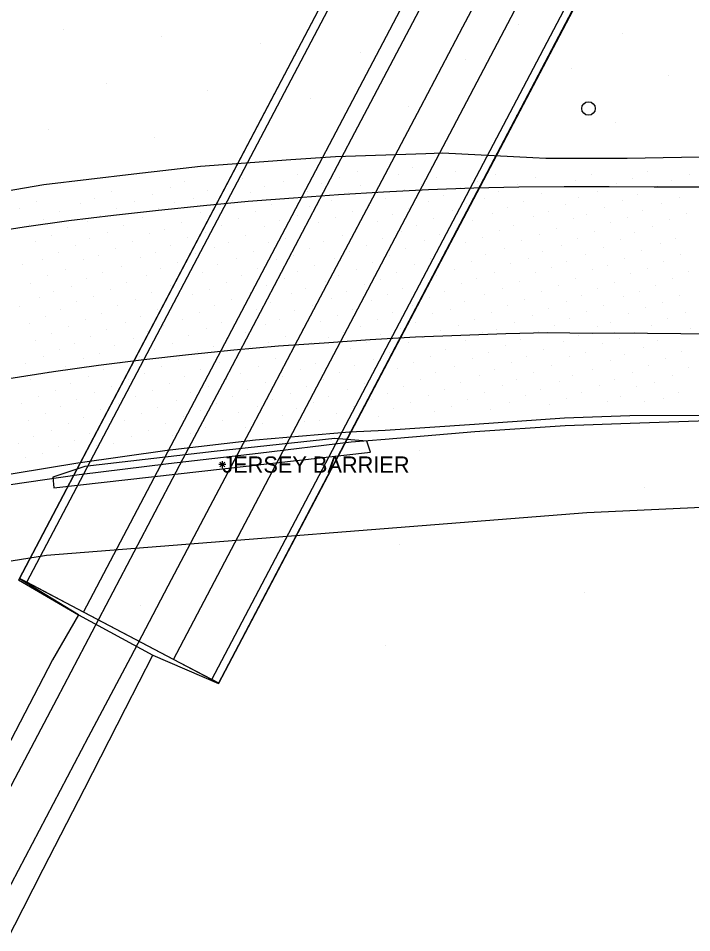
# Model space of a CAD drawing. Extents: x 1732346 to 1733076, y 467730 to 468633.
# Drawn here: x 1732639.2 to 1732713.8, y 467892.4 to 467993.7 of the extents above; entities that cross this region are included whole.
import ezdxf

# ---------------------------------------------------------------- set-up
doc = ezdxf.new("R2010")
doc.units = 0
for name, color, linetype in [('Default', 7, 'Continuous'), ('S_Bridge_BoxCulvert', 7, 'Continuous'), ('S_Ground_Elevation', 7, 'Continuous'), ('S_Ground_LevelString', 7, 'Continuous'), ('S_Ground_SpotElevation', 7, 'Continuous'), ('S_Guardrail_Beam', 7, 'Continuous'), ('S_Guardrail_JerseyBarrier', 7, 'Continuous'), ('S_Misc_MiscItems', 7, 'Continuous'), ('S_Railroad_Tracks', 7, 'Continuous'), ('S_Roadway_Edge_Pavement', 7, 'Continuous'), ('S_Roadway_Painted_Lines', 7, 'Continuous'), ('S_Text', 7, 'Continuous'), ('S_Traffic_Posts', 7, 'Continuous'), ('S_Trees_Bush_Line', 7, 'Continuous'), ('TopoDOT Temp', 7, 'Continuous')]:
    doc.layers.add(name, color=color, linetype=linetype)

# ---------------------------------------------------------------- blocks, each defined once
blk = doc.blocks.new('POINT_DISPLAY')
at = {"layer": 'Default'}
blk.add_line((0, 0), (0, 0), dxfattribs=at)

msp = doc.modelspace()

# ---------------------------------------------------------------- linework, layer by layer
at = {"layer": 'S_Bridge_BoxCulvert'}
for p, q in [((1732639.35, 467931.59), (1732772.73, 468185.16)), ((1732639.36, 467931.62), (1732772.74, 468185.19)), ((1732640.16, 467931.2), (1732773.54, 468184.77)), ((1732646.44, 467927.9), (1732779.82, 468181.46)), ((1732656.4, 467922.66), (1732789.78, 468176.22)), ((1732660.64, 467920.43), (1732794.02, 468173.99)), ((1732661.39, 467920), (1732794.77, 468173.57)), ((1732661.44, 467920.01), (1732794.82, 468173.57)), ((1732639.59, 467932.1), (1732639.59, 467932.1)), ((1732662.35, 467921.99), (1732662.35, 467921.99))]:
    msp.add_line(p, q, dxfattribs=at)
msp.add_lwpolyline([(1732661.39, 467920), (1732661.44, 467920.01), (1732660.64, 467920.43), (1732656.4, 467922.66), (1732646.44, 467927.9), (1732640.16, 467931.2), (1732639.36, 467931.62), (1732639.35, 467931.59)], dxfattribs=at)
at = {"layer": 'S_Ground_Elevation'}
for points in [[(1732645.88, 467927.6), (1732643.01, 467922.59), (1732638.39, 467913.72), (1732633.76, 467904.86), (1732631.44, 467900.41), (1732626.81, 467891.55), (1732622.18, 467882.68), (1732617.56, 467873.82), (1732615.12, 467869.15), (1732610.49, 467860.28), (1732605.86, 467851.42), (1732603.58, 467847.03)], [(1732612.36, 467841.68), (1732616.92, 467850.58), (1732621.49, 467859.48), (1732626.05, 467868.38), (1732630.62, 467877.27), (1732635.18, 467886.17), (1732639.75, 467895.07), (1732641.98, 467899.42), (1732646.55, 467908.32), (1732651.11, 467917.22), (1732654.14, 467923.12)]]:
    msp.add_lwpolyline(points, dxfattribs=at)
at = {"layer": 'S_Ground_LevelString'}
for p, q in [((1732639.24, 467931.46), (1732639.35, 467931.59)), ((1732639.24, 467931.46), (1732645.88, 467927.6)), ((1732639.36, 467931.62), (1732639.35, 467931.59)), ((1732645.88, 467927.6), (1732639.35, 467931.59)), ((1732645.88, 467927.6), (1732654.14, 467923.12)), ((1732654.14, 467923.12), (1732661.39, 467920))]:
    msp.add_line(p, q, dxfattribs=at)
msp.add_lwpolyline([(1732639.36, 467931.62), (1732640.16, 467931.2), (1732660.64, 467920.43), (1732661.44, 467920.01), (1732661.39, 467920)], dxfattribs=at)
at = {"layer": 'S_Guardrail_Beam'}
msp.add_lwpolyline([(1732716.65, 467949.12), (1732706.99, 467948.77), (1732699.77, 467948.52), (1732689.79, 467947.86), (1732679.84, 467947.01), (1732676.08, 467946.7), (1732665.79, 467945.45), (1732655.86, 467944.31), (1732645.98, 467943.08), (1732628.68, 467940.59), (1732625.06, 467940.03), (1732617.13, 467938.47), (1732607.4, 467936.29), (1732607.28, 467936.26), (1732588.1, 467930.71)], dxfattribs=at)
at = {"layer": 'S_Guardrail_JerseyBarrier'}
msp.add_lwpolyline([(1732678.23, 467945.61), (1732677.84, 467946.82), (1732674.27, 467947.12), (1732660.9, 467945.69), (1732646.6, 467944), (1732643.05, 467942.83), (1732643.16, 467941.67), (1732678.23, 467945.61)], dxfattribs=at)
at = {"layer": 'S_Misc_MiscItems'}
for p, q in [((1732662.08, 467943.97), (1732661.56, 467944.49)), ((1732662.08, 467944.49), (1732661.56, 467943.97)), ((1732661.82, 467944.62), (1732661.82, 467943.84)), ((1732662.21, 467944.23), (1732661.43, 467944.23))]:
    msp.add_line(p, q, dxfattribs=at)
at = {"layer": 'S_Railroad_Tracks'}
for points in [[(1732693.1, 468001.52), (1732688.43, 467992.68), (1732683.77, 467983.83), (1732679.11, 467974.98), (1732674.44, 467966.14), (1732669.78, 467957.29), (1732665.11, 467948.45), (1732660.45, 467939.6), (1732655.79, 467930.75), (1732651.64, 467922.88), (1732646.97, 467914.03), (1732642.31, 467905.19), (1732637.65, 467896.34), (1732636.52, 467894.21), (1732631.86, 467885.36)], [(1732627.08, 467887.08), (1732631.74, 467895.93), (1732634.22, 467900.64), (1732638.87, 467909.49), (1732643.53, 467918.34), (1732648.19, 467927.19), (1732652.84, 467936.04), (1732657.5, 467944.89), (1732662.16, 467953.74), (1732666.82, 467962.59), (1732671.47, 467971.44), (1732676.13, 467980.29), (1732680.79, 467989.14), (1732685.44, 467997.99)]]:
    msp.add_lwpolyline(points, dxfattribs=at)
at = {"layer": 'S_Roadway_Edge_Pavement'}
for points in [[(1732600.62, 467966.95), (1732605.6, 467968.27), (1732615.38, 467970.35), (1732623.8, 467972.14), (1732633.66, 467973.82), (1732642.07, 467975.25), (1732652.01, 467976.42), (1732659.41, 467977.29), (1732669.39, 467978), (1732674.35, 467978.35), (1732684.34, 467978.69), (1732686.22, 467978.76), (1732696.2, 467978.22), (1732697.64, 467978.15), (1732706.25, 467978.15), (1732706.66, 467978.15), (1732716.66, 467978.36)], [(1732587.85, 467931.51), (1732607.07, 467937.03), (1732607.21, 467937.06), (1732616.96, 467939.29), (1732624.9, 467940.88), (1732628.53, 467941.58), (1732645.8, 467944.41), (1732655.7, 467945.83), (1732665.51, 467946.97), (1732675.9, 467947.87), (1732679.84, 467948.06), (1732689.74, 467948.7), (1732699.72, 467949.4), (1732706.95, 467949.66), (1732717.62, 467949.7)]]:
    msp.add_lwpolyline(points, dxfattribs=at)
at = {"layer": 'S_Roadway_Painted_Lines'}
for points in [[(1732714.66, 467974.97), (1732709.66, 467974.97), (1732704.66, 467974.98), (1732699.66, 467974.98), (1732694.66, 467974.95), (1732689.66, 467974.85), (1732684.66, 467974.66), (1732679.67, 467974.39), (1732674.68, 467974.09), (1732669.69, 467973.75), (1732664.7, 467973.35), (1732659.72, 467972.89), (1732654.75, 467972.36), (1732649.78, 467971.81), (1732644.81, 467971.21), (1732639.86, 467970.52), (1732634.91, 467969.76), (1732629.98, 467968.93), (1732625.06, 467968.02), (1732620.15, 467967.05), (1732615.26, 467966.01), (1732610.38, 467964.91), (1732605.52, 467963.74), (1732600.68, 467962.48)], [(1732638.18, 467953.78), (1732643.13, 467954.54), (1732648.1, 467955.23), (1732653.13, 467955.86), (1732658.09, 467956.44), (1732663.08, 467956.94), (1732668.05, 467957.38), (1732673.1, 467957.73), (1732678.2, 467958.1), (1732683.21, 467958.36), (1732688.25, 467958.58), (1732693.2, 467958.73), (1732697.82, 467958.87), (1732702.78, 467958.77), (1732705.2, 467958.82), (1732712.6, 467958.76), (1732717.93, 467958.68)]]:
    msp.add_lwpolyline(points, dxfattribs=at)
at = {"layer": 'S_Traffic_Posts'}
msp.add_circle((1732702.37, 467983.67), 0.749, dxfattribs=at)
at = {"layer": 'S_Trees_Bush_Line'}
for points in [[(1732642.36, 467934.2), (1732702.19, 467938.94), (1732749.16, 467941.12), (1732770.02, 467940.5), (1732820.12, 467934.82), (1732875.32, 467924.75), (1732924.72, 467916.03), (1732963.52, 467908.47), (1733004.95, 467900.18), (1733036.67, 467893.23)], [(1732378.87, 467730.2), (1732418.68, 467785.25), (1732451.46, 467829.57), (1732481.42, 467856.92), (1732516.44, 467887.67), (1732559.01, 467910.48), (1732592.36, 467920.81), (1732609.83, 467928.98), (1732642.36, 467934.2)]]:
    msp.add_lwpolyline(points, dxfattribs=at)
at = {"layer": 'TopoDOT Temp'}
for p, q in [((1732688.43, 467992.68), (1732688.43, 467992.68)), ((1732680.79, 467989.14), (1732680.79, 467989.14)), ((1732683.77, 467983.83), (1732683.77, 467983.83)), ((1732676.13, 467980.29), (1732676.13, 467980.29)), ((1732679.11, 467974.98), (1732679.11, 467974.98)), ((1732671.47, 467971.44), (1732671.47, 467971.44)), ((1732674.44, 467966.14), (1732674.44, 467966.14)), ((1732666.82, 467962.59), (1732666.82, 467962.59)), ((1732669.78, 467957.29), (1732669.78, 467957.29)), ((1732662.16, 467953.74), (1732662.16, 467953.74)), ((1732665.11, 467948.45), (1732665.11, 467948.45)), ((1732657.5, 467944.89), (1732657.5, 467944.89)), ((1732660.45, 467939.6), (1732660.45, 467939.6)), ((1732652.84, 467936.04), (1732652.84, 467936.04)), ((1732655.79, 467930.75), (1732655.79, 467930.75)), ((1732645.88, 467927.6), (1732645.88, 467927.6)), ((1732645.88, 467927.6), (1732645.88, 467927.6)), ((1732648.19, 467927.19), (1732648.19, 467927.19)), ((1732654.14, 467923.12), (1732654.14, 467923.12)), ((1732654.14, 467923.12), (1732654.14, 467923.12)), ((1732643.01, 467922.59), (1732643.01, 467922.59)), ((1732651.64, 467922.88), (1732651.64, 467922.88)), ((1732643.53, 467918.34), (1732643.53, 467918.34)), ((1732651.11, 467917.22), (1732651.11, 467917.22)), ((1732646.97, 467914.03), (1732646.97, 467914.03)), ((1732646.55, 467908.32), (1732646.55, 467908.32)), ((1732642.31, 467905.19), (1732642.31, 467905.19)), ((1732641.98, 467899.42), (1732641.98, 467899.42)), ((1732639.75, 467895.07), (1732639.75, 467895.07))]:
    msp.add_line(p, q, dxfattribs=at)

# ---------------------------------------------------------------- block references
at = {"layer": 'S_Ground_SpotElevation'}
for p in [(1732644.23, 467992.44), (1732694.66, 467992.99), (1732655.04, 467991.64), (1732706.16, 467991.92), (1732666.02, 467990.87), (1732677.13, 467989.89), (1732688.76, 467989.04), (1732700.52, 467988.12), (1732711.25, 467987.34), (1732648.98, 467986.48), (1732660.17, 467985.71), (1732671.57, 467984.72), (1732682.44, 467983.91), (1732694.37, 467982.93), (1732705.33, 467982.14), (1732642.56, 467981.36), (1732654.34, 467980.43), (1732682.85, 467977.1), (1732664.07, 467975.92), (1732670.11, 467976.39), (1732674.81, 467975.99), (1732676.78, 467976.68), (1732681.35, 467976.38), (1732685.57, 467976.02), (1732687.6, 467976.72), (1732692.09, 467976.39), (1732696.54, 467975.99), (1732702.65, 467976.31), (1732707.2, 467975.96), (1732708.91, 467976.67), (1732713.59, 467976.38), (1732656.13, 467974.92), (1732657.65, 467975.55), (1732662.34, 467975.24), (1732666.54, 467975.02), (1732668.62, 467975.63), (1732672.84, 467975.41), (1732677.07, 467975.15), (1732679.37, 467975.62), (1732683.92, 467975.23), (1732688.17, 467974.96), (1732690.12, 467975.59), (1732694.46, 467975.24), (1732699.1, 467975), (1732700.92, 467975.74), (1732705.42, 467975.37), (1732710.01, 467975.07), (1732711.61, 467975.67), (1732649.57, 467974.43), (1732654.08, 467974.16), (1732660.14, 467974.54), (1732664.96, 467974.41), (1732671.2, 467974.46), (1732675.8, 467974.32), (1732682.03, 467974.71), (1732686.27, 467974.05), (1732692.41, 467974.52), (1732697.12, 467974.3), (1732701.31, 467973.8), (1732703.37, 467974.46), (1732707.8, 467974.17), (1732712.44, 467973.77), (1732641.24, 467973.35), (1732646.06, 467973.11), (1732647.61, 467973.68), (1732652.14, 467973.33), (1732656.48, 467973.29), (1732658.62, 467973.73), (1732662.95, 467973.46), (1732667.25, 467972.98), (1732669.05, 467973.7), (1732671.5, 467972.78), (1732673.95, 467973.46), (1732678.12, 467972.93), (1732679.89, 467973.68), (1732684.65, 467973.41), (1732688.83, 467973.11), (1732690.85, 467973.75), (1732695.15, 467973.36), (1732699.82, 467973.02), (1732704.11, 467972.75), (1732706.14, 467973.48), (1732710.51, 467973.09), (1732639.39, 467972.6), (1732643.81, 467972.26), (1732648.32, 467971.83), (1732650.08, 467972.64), (1732654.74, 467972.64), (1732659.41, 467972.16), (1732660.94, 467972.54), (1732665.46, 467972.21), (1732670.16, 467971.87), (1732676.27, 467972.23), (1732680.63, 467971.89), (1732682.43, 467972.61), (1732687.28, 467972.34), (1732691.77, 467972.01), (1732693.37, 467972.73), (1732697.93, 467972.26), (1732702.17, 467971.88), (1732708.37, 467972.32), (1732713.24, 467972.09), (1732640.47, 467970.83), (1732642.07, 467971.41), (1732646.84, 467971.17), (1732650.85, 467970.73), (1732652.96, 467971.57), (1732657.3, 467971.05), (1732661.74, 467970.72), (1732663.62, 467971.45), (1732668.14, 467971.22), (1732672.46, 467971.05), (1732674.37, 467971.56), (1732678.99, 467971.18), (1732685.17, 467971.47), (1732689.58, 467971.21), (1732694.02, 467970.75), (1732696.27, 467971.69), (1732700.67, 467971.46), (1732704.79, 467971), (1732706.7, 467971.58), (1732711.36, 467971.37), (1732644.67, 467970.51), (1732649.12, 467969.98), (1732653.76, 467969.81), (1732655.37, 467970.3), (1732660, 467969.97), (1732666.47, 467970.64), (1732670.67, 467970), (1732676.8, 467970.41), (1732681.67, 467970.08), (1732683.29, 467970.69), (1732687.73, 467970.4), (1732692.51, 467970.17), (1732696.93, 467969.71), (1732698.78, 467970.42), (1732703, 467970.01), (1732707.47, 467969.96), (1732709.51, 467970.58), (1732641.17, 467968.99), (1732642.91, 467969.55), (1732647.15, 467969.24), (1732651.89, 467968.94), (1732657.97, 467969.37), (1732662.46, 467968.87), (1732664.41, 467969.6), (1732666.94, 467968.77), (1732668.84, 467969.25), (1732673.03, 467968.99), (1732675.14, 467969.58), (1732679.56, 467969.32), (1732684.25, 467969.04), (1732685.92, 467969.66), (1732688.75, 467968.8), (1732690.65, 467969.35), (1732694.98, 467969.01), (1732701.2, 467969.27), (1732705.89, 467969.11), (1732710.32, 467968.72), (1732712.01, 467969.3), (1732643.7, 467967.69), (1732645.55, 467968.47), (1732649.98, 467968.11), (1732654.38, 467967.71), (1732656.13, 467968.44), (1732660.97, 467968.3), (1732665.22, 467967.79), (1732671.43, 467968.13), (1732675.85, 467967.79), (1732677.82, 467968.48), (1732682.14, 467968.15), (1732686.43, 467967.85), (1732693.02, 467968.17), (1732697.3, 467967.86), (1732699.42, 467968.5), (1732704.01, 467968.3), (1732708.19, 467967.96), (1732641.87, 467966.98), (1732646.41, 467966.93), (1732648.15, 467967.35), (1732652.75, 467967.16), (1732658.88, 467967.57), (1732663.35, 467967.02), (1732667.77, 467966.91), (1732669.66, 467967.39), (1732674.21, 467967), (1732680.29, 467967.37), (1732684.9, 467967.01), (1732689.45, 467966.68), (1732691.01, 467967.48), (1732695.68, 467967.01), (1732699.96, 467966.71), (1732702.02, 467967.49), (1732706.36, 467967.01), (1732710.73, 467966.7), (1732712.6, 467967.49), (1732639.72, 467966.37), (1732644.5, 467965.86), (1732650.61, 467966.21), (1732654.97, 467965.91), (1732656.88, 467966.63), (1732661.32, 467966.41), (1732665.73, 467965.97), (1732672.05, 467966.28), (1732676.69, 467965.89), (1732678.48, 467966.65), (1732683.14, 467966.36), (1732687.56, 467965.89), (1732693.78, 467966.53), (1732698.27, 467966.11), (1732702.81, 467965.78), (1732704.52, 467966.32), (1732708.94, 467965.92), (1732642.48, 467965.18), (1732646.74, 467964.89), (1732648.59, 467965.54), (1732653.39, 467965.12), (1732657.95, 467964.8), (1732659.68, 467965.52), (1732663.92, 467965.16), (1732668.67, 467964.79), (1732670.17, 467965.56), (1732674.67, 467965.14), (1732679.31, 467964.76), (1732681.16, 467965.52), (1732685.58, 467965.21), (1732689.94, 467964.83), (1732691.99, 467965.52), (1732696.55, 467965.47), (1732700.95, 467964.83), (1732706.97, 467965.44), (1732711.66, 467964.84), (1732713.41, 467965.6), (1732640.61, 467964.33), (1732645.17, 467963.98), (1732651.2, 467964.42), (1732656.04, 467964.01), (1732662.3, 467964.4), (1732666.74, 467964.04), (1732670.98, 467963.76), (1732673.21, 467964.51), (1732677.59, 467964.13), (1732681.77, 467963.75), (1732683.72, 467964.4), (1732688.31, 467964.26), (1732692.84, 467963.76), (1732694.68, 467964.51), (1732699.07, 467964.06), (1732703.39, 467963.68), (1732705.22, 467964.41), (1732709.74, 467964.1), (1732641.61, 467962.71), (1732643.08, 467963.44), (1732647.59, 467962.86), (1732649.47, 467963.6), (1732653.98, 467963.34), (1732658.5, 467963.02), (1732660.35, 467963.62), (1732664.99, 467963.32), (1732669.48, 467963.13), (1732673.88, 467962.67), (1732675.57, 467963.37), (1732680.07, 467963.12), (1732684.72, 467962.73), (1732686.45, 467963.44), (1732690.87, 467963.08), (1732697.18, 467963.4), (1732701.55, 467962.98), (1732706.25, 467962.8), (1732707.97, 467963.36), (1732712.47, 467962.99), (1732639.39, 467961.76), (1732645.63, 467962.26), (1732650.2, 467961.81), (1732652.21, 467962.49), (1732656.62, 467962.28), (1732660.9, 467961.84), (1732662.83, 467962.52), (1732667.21, 467962.19), (1732671.78, 467961.81), (1732678.29, 467962.4), (1732682.84, 467961.9), (1732688.65, 467962.3), (1732693.43, 467961.87), (1732695.25, 467962.55), (1732699.92, 467962.3), (1732704.03, 467961.83), (1732708.63, 467961.63), (1732710.53, 467962.23), (1732642.26, 467960.63), (1732643.87, 467961.38), (1732648.49, 467961), (1732652.76, 467960.66), (1732654.66, 467961.4), (1732659.29, 467961.02), (1732663.65, 467960.64), (1732665.61, 467961.4), (1732669.79, 467961.26), (1732674.59, 467960.73), (1732676.26, 467961.46), (1732680.7, 467961.1), (1732685.13, 467960.91), (1732687.04, 467961.46), (1732691.59, 467961.11), (1732696.16, 467960.79), (1732697.94, 467961.57), (1732702.19, 467961.22), (1732706.85, 467960.92), (1732713.07, 467961.11), (1732640.44, 467959.91), (1732646.64, 467960.33), (1732651.12, 467959.98), (1732655.36, 467959.58), (1732657.38, 467960.28), (1732661.77, 467959.94), (1732666.56, 467959.76), (1732668.19, 467960.31), (1732672.66, 467960.07), (1732678.99, 467960.31), (1732683.18, 467960.02), (1732688.02, 467959.64), (1732689.72, 467960.34), (1732694.14, 467959.95), (1732698.61, 467959.59), (1732700.28, 467960.37), (1732704.82, 467959.97), (1732709.35, 467959.65), (1732711.17, 467960.36), (1732642.9, 467958.75), (1732644.76, 467959.56), (1732649.02, 467959.2), (1732653.54, 467958.94), (1732660.07, 467959.29), (1732664.36, 467958.82), (1732670.66, 467959.23), (1732675.23, 467958.84), (1732677.14, 467959.57), (1732679.39, 467958.62), (1732681.54, 467959.25), (1732686.01, 467959.12), (1732690.67, 467958.81), (1732692.16, 467959.24), (1732696.81, 467959), (1732703.32, 467959.52), (1732707.5, 467958.86), (1732712.14, 467958.75), (1732713.66, 467959.26), (1732641.1, 467958.01), (1732645.47, 467957.68), (1732647.17, 467958.42), (1732651.94, 467958.14), (1732656.33, 467957.68), (1732658.08, 467958.49), (1732662.5, 467958.14), (1732666.88, 467957.74), (1732668.87, 467958.47), (1732671.66, 467957.77), (1732673.59, 467958.29), (1732677.81, 467957.7), (1732682.45, 467957.71), (1732683.94, 467958.27), (1732688.76, 467957.99), (1732694.86, 467958.08), (1732699.59, 467957.85), (1732701.22, 467958.49), (1732703.87, 467957.68), (1732705.81, 467958.15), (1732710.03, 467957.97), (1732643.8, 467956.98), (1732648.17, 467956.54), (1732649.87, 467957.42), (1732654.3, 467956.95), (1732659.04, 467956.71), (1732660.79, 467957.32), (1732664.9, 467957.32), (1732669.55, 467956.7), (1732676.03, 467957.08), (1732680.34, 467956.61), (1732686.51, 467957.02), (1732691.35, 467956.68), (1732693.19, 467957.39), (1732697.36, 467957.01), (1732702.05, 467956.64), (1732708.48, 467957.24), (1732712.69, 467956.8), (1732641.97, 467956.22), (1732646.41, 467956), (1732652.6, 467956.2), (1732656.99, 467955.82), (1732663.48, 467956.33), (1732667.73, 467955.93), (1732674, 467956.24), (1732678.52, 467955.85), (1732682.97, 467955.53), (1732684.92, 467956.22), (1732689.54, 467955.98), (1732695.52, 467956.24), (1732700.25, 467956.19), (1732704.79, 467955.77), (1732706.38, 467956.46), (1732710.89, 467955.97), (1732639.99, 467955.42), (1732642.61, 467954.56), (1732644.49, 467955.09), (1732648.68, 467954.75), (1732650.55, 467955.48), (1732655.1, 467955.08), (1732659.44, 467954.74), (1732661.56, 467955.51), (1732665.79, 467955.11), (1732670.51, 467954.79), (1732672.14, 467955.46), (1732676.5, 467955.18), (1732681.17, 467954.85), (1732687.49, 467955.11), (1732691.94, 467954.75), (1732693.88, 467955.52), (1732698.29, 467955.17), (1732702.84, 467954.81), (1732709.04, 467955.19), (1732713.49, 467954.96), (1732640.59, 467953.68), (1732647, 467953.96), (1732651.41, 467953.63), (1732653.24, 467954.31), (1732657.66, 467953.96), (1732662.33, 467953.61), (1732663.88, 467954.37), (1732668.53, 467953.96), (1732673.01, 467953.64), (1732674.8, 467954.38), (1732679.33, 467954.01), (1732683.8, 467953.62), (1732685.42, 467954.47), (1732690.31, 467954.13), (1732694.44, 467953.63), (1732696.3, 467954.48), (1732700.61, 467954.13), (1732705.29, 467953.66), (1732707.25, 467954.42), (1732711.63, 467954.07), (1732645, 467953.2), (1732649.53, 467952.87), (1732655.93, 467953.22), (1732660.31, 467952.92), (1732664.59, 467952.56), (1732666.65, 467953.33), (1732671.09, 467952.91), (1732675.69, 467952.56), (1732677.52, 467953.24), (1732681.92, 467952.87), (1732686.45, 467952.56), (1732688.25, 467953.28), (1732692.82, 467952.99), (1732697.02, 467952.57), (1732699.19, 467953.45), (1732703.63, 467953), (1732707.7, 467952.89), (1732709.71, 467953.3), (1732641.5, 467951.72), (1732643.34, 467952.48), (1732647.68, 467952.17), (1732652.23, 467951.79), (1732654.05, 467952.47), (1732658.25, 467952.24), (1732662.94, 467951.75), (1732669.33, 467952.14), (1732673.63, 467951.77), (1732680.08, 467952.12), (1732684.66, 467951.84), (1732690.89, 467952.17), (1732695.39, 467951.86), (1732699.91, 467951.5), (1732701.55, 467952.19), (1732705.92, 467951.82), (1732710.7, 467951.53), (1732712.38, 467952.2), (1732639.53, 467950.95), (1732643.87, 467950.67), (1732645.7, 467951.45), (1732650.37, 467951.02), (1732654.69, 467950.6), (1732656.78, 467951.38), (1732661.23, 467951.01), (1732665.68, 467950.67), (1732667.42, 467951.39), (1732670.01, 467950.48), (1732671.87, 467951.09), (1732676.36, 467950.7), (1732678.31, 467951.41), (1732682.61, 467951.07), (1732687.19, 467950.71), (1732689, 467951.41), (1732693.59, 467951.12), (1732698.06, 467950.83), (1732704.44, 467951.19), (1732708.54, 467951.25), (1732642.21, 467949.89), (1732646.47, 467949.49), (1732648.36, 467950.31), (1732652.83, 467949.87), (1732657.47, 467949.52), (1732659.36, 467950.26), (1732663.59, 467949.96), (1732668.43, 467949.68), (1732674.51, 467949.93), (1732679.08, 467949.57), (1732680.77, 467950.39), (1732685.27, 467950.07), (1732691.57, 467950.38), (1732640.36, 467949.11), (1732644.83, 467948.76), (1732651.02, 467949.16), (1732655.56, 467948.81), (1732661.81, 467949.13), (1732666.29, 467948.79), (1732670.95, 467948.97), (1732672.63, 467949.13), (1732676.98, 467949.42), (1732642.87, 467948.02), (1732647.16, 467947.67), (1732649.16, 467948.38), (1732653.66, 467948.05), (1732656.31, 467947.47), (1732658.28, 467947.67), (1732659.95, 467948.39), (1732664.37, 467948.38), (1732639.25, 467946.54), (1732640.91, 467947.3), (1732645.48, 467946.94), (1732649.82, 467946.58), (1732651.81, 467947.34), (1732641.89, 467945.41), (1732643.69, 467946.21), (1732647.89, 467946.32), (1732683.64, 467945.79), (1732640.07, 467945), (1732708.57, 467941.67), (1732681.44, 467935.43), (1732701.91, 467930.04), (1732652.72, 467928.63), (1732679.93, 467924.2)]:
    msp.add_blockref('POINT_DISPLAY', p, dxfattribs=at)

# ---------------------------------------------------------------- texts
at = {"layer": 'S_Text'}
msp.add_text('JERSEY BARRIER', height=1.8, dxfattribs=at).set_placement((1732661.82, 467943.33))

doc.saveas('drawing.dxf')
